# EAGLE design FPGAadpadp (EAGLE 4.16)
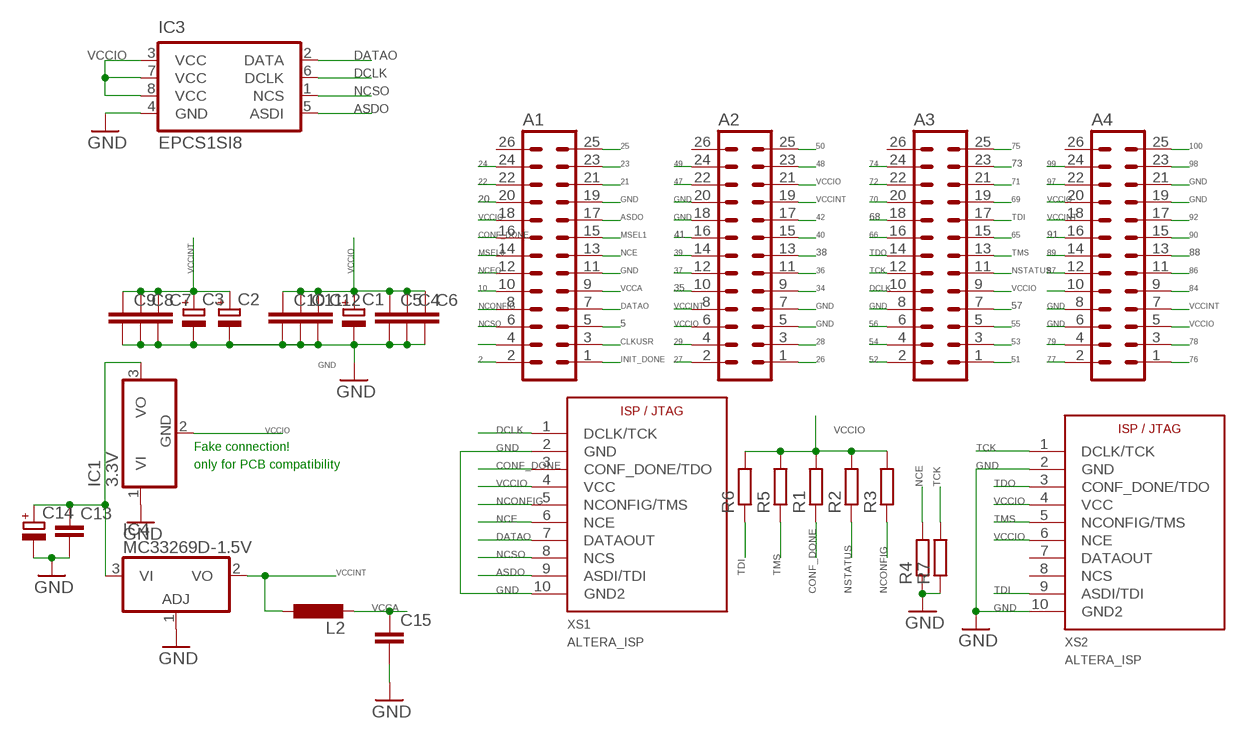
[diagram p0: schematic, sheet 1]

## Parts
A1  ML26  [ML26]
A2  ML26  [ML26]
A3  ML26  [ML26]
A4  ML26  [ML26]
C1  CPOL-EUC/6032-28R  [C/6032-28R]
C2  CPOL-EUC/6032-28R  [C/6032-28R]
C3  CPOL-EUC/6032-28R  [C/6032-28R]
C4  C-EUC1206  [C1206]
C5  C-EUC1206  [C1206]
C6  C-EUC1206  [C1206]
C7  C-EUC1206  [C1206]
C8  C-EUC1206  [C1206]
C9  C-EUC1206  [C1206]
C10  C-EUC1206  [C1206]
C11  C-EUC1206  [C1206]
C12  C-EUC1206  [C1206]
C13  C-EUC1206  [C1206]
C14  CPOL-EUC/6032-28R  [C/6032-28R]
C15  C-EUC1206  [C1206]
IC1  3.3V  LM2937  [TO263-3]
IC3  EPCS1SI8  [SO08]
IC4  MC33269D-1.5V  MC33269D-3.3  [DPACK]
L2  L-EUL4532P  [L4532P]
R1  R-EU_M1206  [M1206]
R2  R-EU_M1206  [M1206]
R3  R-EU_M1206  [M1206]
R4  R-EU_M1206  [M1206]
R5  R-EU_M1206  [M1206]
R6  R-EU_M1206  [M1206]
R7  R-EU_M1206  [M1206]
XS1  ALTERA_ISP  [ALTERA_ISP]
XS2  ALTERA_ISP  [ALTERA_ISP]

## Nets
2: A1.2
4: A1.4
5: A1.5
10: A1.10
20: A1.20
21: A1.21
22: A1.22
23: A1.23
24: A1.24
25: A1.25
26: A2.1
27: A2.2
28: A2.3
29: A2.4
34: A2.9
35: A2.10
36: A2.11
37: A2.12
38: A2.13
39: A2.14
40: A2.15
41: A2.16
42: A2.17
47: A2.22
48: A2.23
49: A2.24
50: A2.25
51: A3.1
52: A3.2
53: A3.3
54: A3.4
55: A3.5
56: A3.6
57: A3.7
65: A3.15
66: A3.16
68: A3.18
69: A3.19
70: A3.20
71: A3.21
72: A3.22
73: A3.23
74: A3.24
75: A3.25
76: A4.1
77: A4.2
78: A4.3
79: A4.4
84: A4.9
85: A4.10
86: A4.11
87: A4.12
88: A4.13
89: A4.14
90: A4.15
91: A4.16
92: A4.17
97: A4.22
98: A4.23
99: A4.24
100: A4.25
ASDO: A1.17 IC3.5(ASDI) XS1.9(ASDI/TDI)
CLKUSR: A1.3
CONF_DONE: A1.16 R1.1 XS1.3(CONF_DONE/TDO)
DATAO: A1.7 IC3.2(DATA) XS1.7(DATAOUT)
DCLK: A3.10 IC3.6(DCLK) XS1.1(DCLK/TCK)
GND: A1.11 A1.19 A2.5 A2.7 A2.18 A2.20 A3.8 A4.6 A4.8 A4.19 A4.21 C1.- C2.- C3.- C4.2 C5.2 C6.2 C7.2 C8.2 C9.2 C10.2 C11.2 C12.2 C13.2 C14.- C15.2 IC1.1(VI) IC3.4(GND) IC4.1(ADJ) R4.1 R7.1 XS1.2(GND) XS1.10(GND2) XS2.2(GND) XS2.10(GND2)
INIT_DONE: A1.1
MSEL0: A1.14
MSEL1: A1.15
NCE: A1.13 R4.2 XS1.6(NCE)
NCEO: A1.12
NCONFIG: A1.8 R3.1 XS1.5(NCONFIG/TMS)
NCSO: A1.6 IC3.1(NCS) XS1.8(NCS)
NSTATUS: A3.11 R2.1
TCK: A3.12 R7.2 XS2.1(DCLK/TCK)
TDI: A3.17 R6.1 XS2.9(ASDI/TDI)
TDO: A3.14 XS2.3(CONF_DONE/TDO)
TMS: A3.13 R5.1 XS2.5(NCONFIG/TMS)
VCC: C13.1 C14.+ IC1.3(VO) IC4.3(VI)
VCCA: A1.9 C15.1 L2.2
VCCINT: A2.8 A2.19 A4.7 A4.18 C2.+ C3.+ C7.1 C8.1 C9.1 IC4.2(VO) L2.1
VCCIO: A1.18 A2.6 A2.21 A3.9 A4.5 A4.20 C1.+ C4.1 C5.1 C6.1 C10.1 C11.1 C12.1 IC1.2(GND) IC3.3(VCC) IC3.7(VCC) IC3.8(VCC) R1.2 R2.2 R3.2 R5.2 R6.2 XS1.4(VCC) XS2.4(VCC) XS2.6(NCE)
Unconnected: A1.26 A2.26 A3.26 A4.26 XS2.7(DATAOUT) XS2.8(NCS)

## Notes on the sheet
- Fake connection!
- only for PCB compatibility

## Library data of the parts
A1-A4 = con-ml:ML26: HARTING
C1-C3 C14 = rcl:CPOL-EU: POLARIZED CAPACITOR, European symbol
C4-C13 C15 = rcl:C-EU: CAPACITOR, European symbol
IC1 = linear:LM2937: LM2937-2.5, LM2937-3.3 400mA and 500mA Voltage Regulators Source: http://cache.national.com/ds/LM/LM2937-2.5.pdf
IC3 = altera-2:EPCS1: 1 Mbit Serial Configuration Device
IC4 = linear:MC33269?*: Adjustable Output Low Dropout Voltage Regulator 800 mA Source: http://www.onsemi.com/pub/Collateral/MC33269-D.PDF
L2 = rcl:L-EU: INDUCTOR, European symbol
R1-R7 = rcl:R-EU_: RESISTOR, European symbol
XS1 XS2 = LevoROMS:ALTERA_ISP

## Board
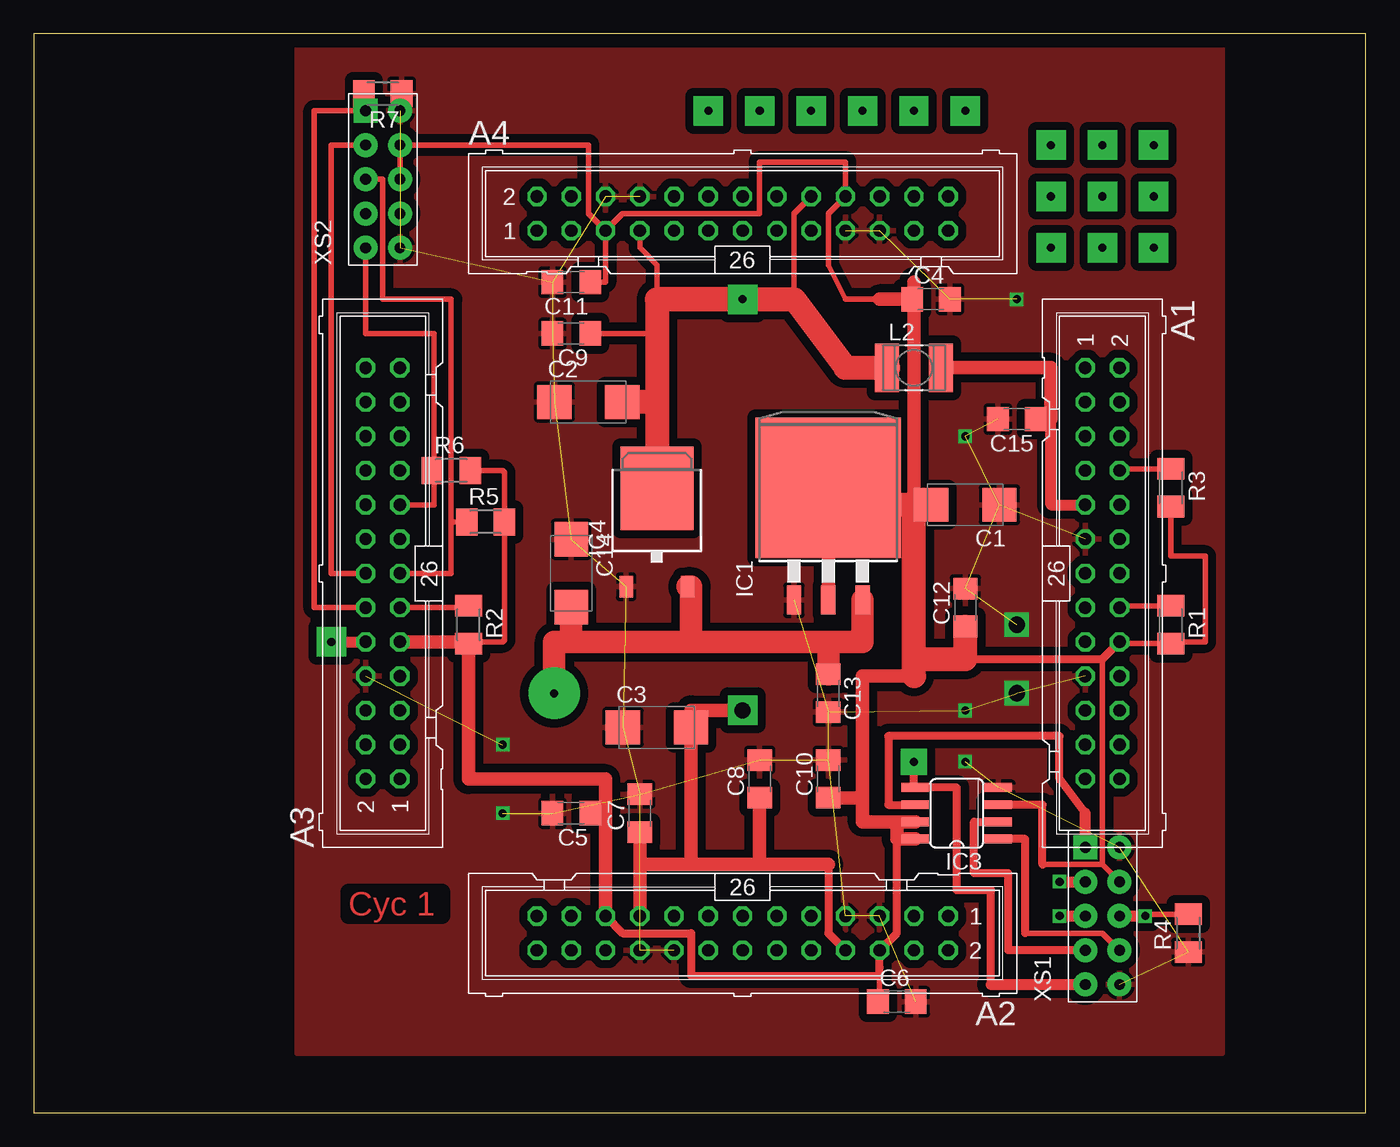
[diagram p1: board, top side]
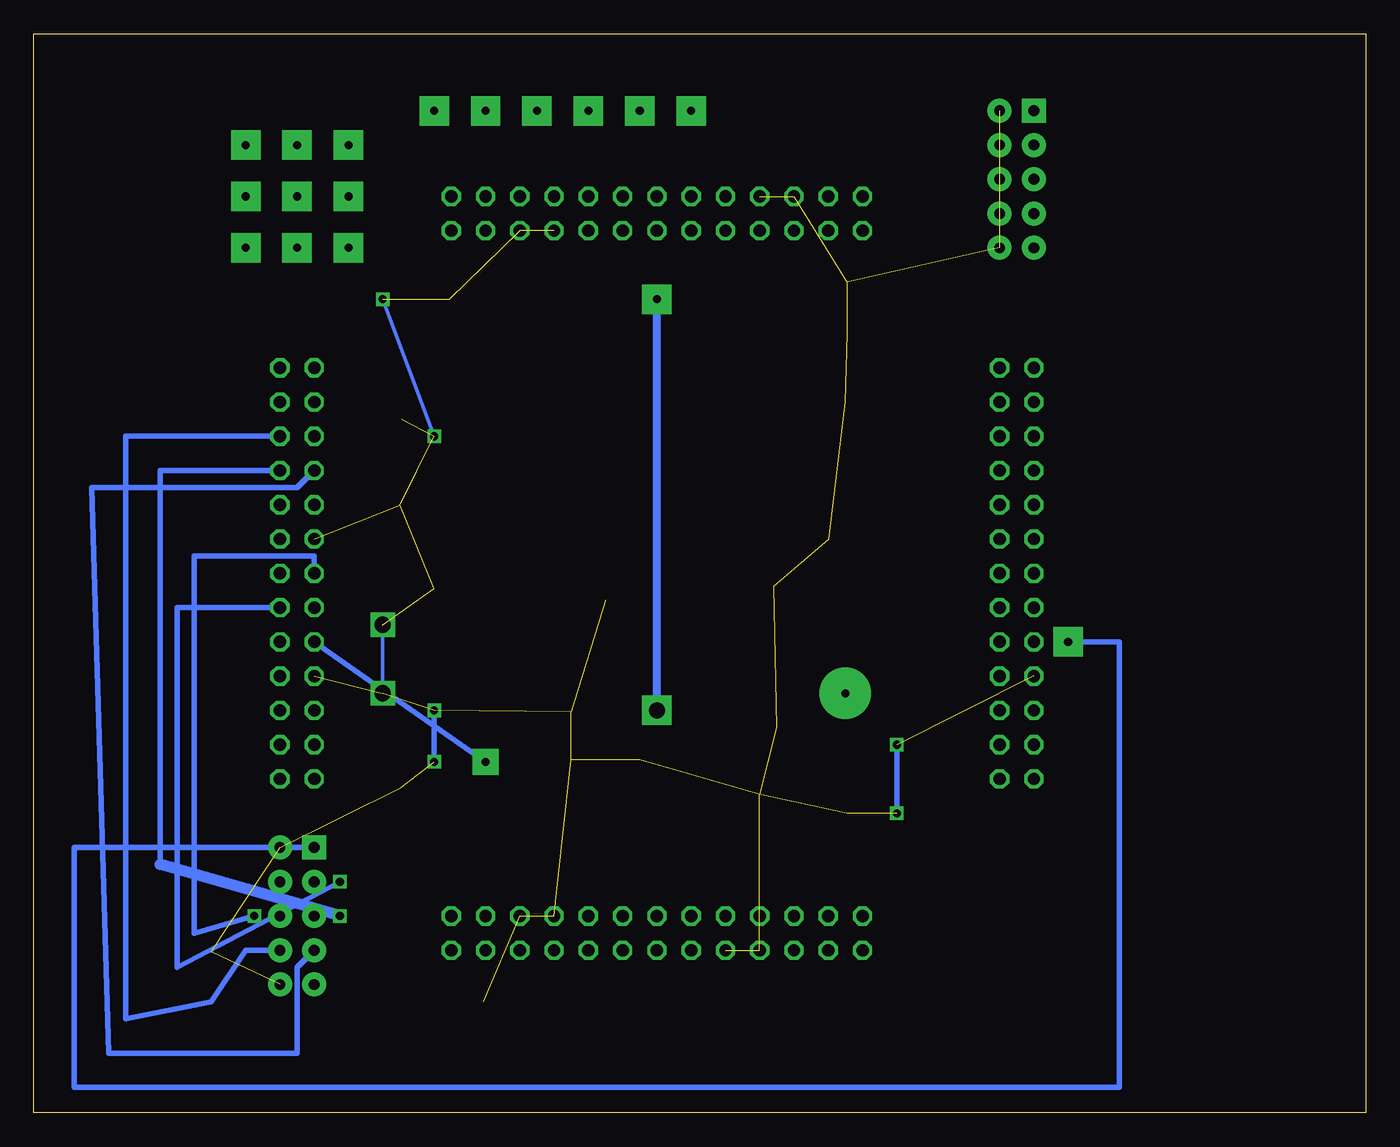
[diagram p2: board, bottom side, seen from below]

Size 98.73 x 80 mm. Coordinates in mm from the lower left corner, seen from the top.
Outline: 0,0 98.73,0 98.73,80 0,80 0,0
Copper layers (1*16): Top 0.035mm / dielectric 1.5mm / Bottom 0.035mm
Design rules "default": minimum track width 10mil, minimum drill 24mil, track to track 8mil, track to pad 8mil, pad to pad 8mil, via to via 8mil, smd to smd 8mil, copper to edge 40mil, drill to drill 8mil, minimum pad ring 10mil, minimum via ring 8mil, stop-mask expansion 4mil, vias tented up to drill 0mil, thermal gap 10mil

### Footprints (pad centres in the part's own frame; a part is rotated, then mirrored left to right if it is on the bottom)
ML26 = drill 0.914 octagon: 1 -15.24,-1.27; 2 -15.24,1.27; 3 -12.7,-1.27; 4 -12.7,1.27; 5 -10.16,-1.27; 6 -10.16,1.27; 7 -7.62,-1.27; 8 -7.62,1.27; 9 -5.08,-1.27; 10 -5.08,1.27; 11 -2.54,-1.27; 12 -2.54,1.27; 13 0,-1.27; 14 0,1.27; 15 2.54,-1.27; 16 2.54,1.27; 17 5.08,-1.27; 18 5.08,1.27; 19 7.62,-1.27; 20 7.62,1.27; 21 10.16,-1.27; 22 10.16,1.27; 23 12.7,-1.27; 24 12.7,1.27; 25 15.24,-1.27; 26 15.24,1.27
C/6032-28R = smd 2.55 x 2.5: + 2.525,0; - -2.525,0
C1206 = smd 1.6 x 1.8: 1 -1.4,0; 2 1.4,0
TO263-3 = smd 1.067 x 2.159: 1 -2.54,-5.791; 2 0,-5.791; 3 2.54,-5.791 | smd 10.8 x 10.41: TAB 0,2.54
SO08 = smd 0.66 x 2.032: 1 -1.905,-3.073; 2 -0.635,-3.073; 3 0.635,-3.073; 4 1.905,-3.073; 5 1.905,3.073; 6 0.635,3.073; 7 -0.635,3.073; 8 -1.905,3.073
DPACK = smd 1 x 1.6: 1 -2.28,-4.8; 3 2.28,-4.8 | smd 5.4 x 6.2: 2 0,2.5
L4532P = smd 1.8 x 3.6: 1 -2,0; 2 2,0
M1206 = smd 1.6 x 2: 1 -1.4,0; 2 1.4,0
ALTERA_ISP = drill 0.8 pad 1.778 square: 1 -1.27,2.54 | drill 0.8 pad 1.778 round: 2 1.27,2.54; 3 -1.27,0; 4 1.27,0; 5 -1.27,-2.54; 6 1.27,-2.54; 7 -1.27,-5.08; 8 1.27,-5.08; 9 -1.27,-7.62; 10 1.27,-7.62

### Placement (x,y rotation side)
A1  79.21,40 270 top
A2  52.54,13.33 180 top
A3  25.87,40 90 top
A4  52.54,66.67 0 top
C1  69.05,45.08 180 top
C2  41.11,52.7 0 top
C3  46.19,28.57 0 top
C4  66.51,60.32 0 top
C5  39.84,22.22 180 top
C6  63.97,8.25 0 top
C7  44.92,22.22 90 top
C8  53.81,24.76 90 top
C9  39.84,57.78 180 top
C10  58.89,24.76 90 top
C11  39.84,61.59 180 top
C12  69.05,37.46 90 top
C13  58.89,31.11 270 top
C14  39.84,40 270 top
C15  72.86,51.43 180 top
IC1  58.89,43.81 0 top
IC3  68.41,22.22 90 top
IC4  46.19,43.81 0 top
L2  65.24,55.24 0 top
R1  84.29,36.19 270 top
R2  32.22,36.19 270 top
R3  84.29,46.35 270 top
R4  85.56,13.33 90 top
R5  33.49,43.81 0 top
R6  30.95,47.62 0 top
R7  25.87,75.56 180 top
XS1  79.21,17.14 0 top
XS2  25.87,71.75 0 top

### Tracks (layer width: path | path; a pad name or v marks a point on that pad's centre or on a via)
ASDO  (via drill 0.6 pad 1.93)
  Top 0.406: IC3.5 arc-180 65.24,24.12
  Top 0.61: IC3.5 68.41,24.12 68.41,16.5 70.95,16.5 70.95,9.52 | 65.24,24.12 v65.24,26.03
  Top 0.813: 70.95,9.52 XS1.9
  Bottom 0.406: v65.24,26.03 A1.17
CONF_DONE  (via drill 0.6)
  Top 0.406: R1.1 80.48,37.59 A1.16
  Top 0.813: v76.03,17.14 XS1.3
  Bottom 0.406: A1.16 88.1,37.46 88.1,10.79 v76.03,17.14
DATAO
  Top 0.61: IC3.2 69.69,21.58 69.69,17.77 72.22,17.77 72.22,12.06 XS1.7
  Bottom 0.406: A1.7 79.21,46.35 94.45,46.35 93.18,4.44 79.21,4.44 79.21,10.79 XS1.7
DCLK  (via drill 0.6 pad 2.18)
  Top 0.61: 77.94,22.22 76.03,24.76 76.03,27.93 63.34,27.93 63.34,22.86 IC3.6
  Top 0.813: XS1.1 77.94,22.22 | v22.06,34.92 A3.10
  Bottom 0.406: XS1.1 95.72,19.68 95.72,1.9 18.25,1.9 18.25,34.92 v22.06,34.92
GND  (via drill 0.6, 1.2)  (37 unrouted)
  Top 0.406: R7.1 27.27,74.42 XS2.2
  Bottom 0.254: v72.86,31.11 v72.86,36.19 | v69.05,50.16 v72.86,60.32
  Bottom 0.406: v69.05,26.03 v69.05,29.84 | v34.76,22.22 v34.76,27.3
  pour Top (isolate 0.61): 19.52,79.37 19.52,4.44 88.1,4.44 88.1,79.37
N$10  (via drill 0.6 pad 2.18)
  other vias: 75.4,71.75
N$11  (via drill 0.6 pad 2.18)
  other vias: 75.4,67.94
N$12  (via drill 0.6 pad 2.18)
  other vias: 75.4,64.13
N$13  (via drill 0.6 pad 2.18)
  other vias: 79.21,64.13
N$14  (via drill 0.6 pad 2.18)
  other vias: 79.21,67.94
N$15  (via drill 0.6 pad 2.18)
  other vias: 79.21,71.75
N$16  (via drill 0.6 pad 2.18)
  other vias: 83.02,71.75
N$17  (via drill 0.6 pad 2.18)
  other vias: 83.02,67.94
N$18  (via drill 0.6 pad 2.18)
  other vias: 83.02,64.13
N$25  (via drill 0.6 pad 2.18)
  other vias: 50,74.29
N$26  (via drill 0.6 pad 2.18)
  other vias: 53.81,74.29
N$27  (via drill 0.6 pad 2.18)
  other vias: 57.62,74.29
N$28  (via drill 0.6 pad 2.18)
  other vias: 61.43,74.29
N$29  (via drill 0.6 pad 2.18)
  other vias: 65.24,74.29
N$30  (via drill 0.6 pad 2.18)
  other vias: 69.05,74.29
NCE  (via drill 0.6)
  Top 0.406: R4.2 80.48,14.73 XS1.6
  Top 0.813: XS1.6 v82.39,14.6
  Bottom 0.406: v82.39,14.6 86.83,13.33 86.83,41.27 77.94,41.27 A1.13
NCONFIG  (via drill 0.6)
  Top 0.406: R3.1 80.48,47.75 A1.8
  Top 0.813: v76.03,14.6 XS1.5
  Bottom 0.406: A1.8 89.37,47.62 89.37,18.41
  Bottom 0.813: v76.03,14.6 89.37,18.41
NCSO
  Top 0.406: 73.5,13.33 79.21,13.33 XS1.8
  Top 0.61: IC3.1 73.5,20.31 73.5,13.33
  Bottom 0.406: A1.6 91.91,50.16 91.91,6.98 85.56,8.25 83.02,12.06 XS1.8
NSTATUS
  Top 0.406: R2.1 32.22,37.46 A3.11
TCK
  Top 0.406: A3.12 20.79,37.46 20.79,74.29 XS2.1 24.47,74.42 R7.2
TDI
  Top 0.406: XS2.9 24.6,57.78 29.68,57.78 29.68,47.62 | 29.68,47.62 29.68,45.08 A3.17 | 29.68,47.62 R6.1
TDO
  Top 0.406: XS2.3 22.06,71.75 22.06,40 A3.14
TMS
  Top 0.406: XS2.5 25.87,69.21 25.87,60.32 30.95,60.32 30.95,43.81 | 30.95,43.81 30.95,40 A3.13 | 30.95,43.81 R5.1
VCC  (via drill 0.6 pad 3.81)
  Top 0.406: IC1.3 61.43,38.1
  Top 1.676: 39.84,34.92 C14.+ | v38.57,31.11 38.57,34.92 39.84,34.92 | 39.84,34.92 48.73,34.92 | 48.73,34.92 58.89,34.92 | 58.89,34.92 61.43,34.92 IC1.3 | IC4.3 48.73,39.01 48.73,34.92 | 58.89,34.92 C13.1
VCCA
  Top 0.813: A1.9 75.4,45.08 75.4,51.43 C15.1
  Top 1.016: 75.4,51.43 75.4,55.24 L2.2
VCCINT  (via drill 0.6 pad 2.18, 1.2 pad 2.18)
  Top 0.406: A4.18 56.35,66.67 56.35,60.32 | 46.19,57.78 C9.1 | A4.7 44.92,64.13 46.19,62.86 46.19,60.32
  Top 0.61: A2.8 58.89,13.33 58.89,18.41
  Top 0.813: 48.73,27.3 C3.+
  Top 1.016: 48.73,18.41 48.73,27.3 48.73,29.84 v52.54,29.84 | 44.92,18.41 48.73,18.41 | 48.73,18.41 53.81,18.41 | 53.81,18.41 C8.1 | 53.81,18.41 58.89,18.41 | 44.92,18.41 C7.1 | A2.19 44.92,18.41
  Top 1.778: 46.19,52.7 IC4.2 | 46.19,52.7 C2.+ | 46.19,60.32 46.19,57.78 46.19,52.7 | v52.54,60.32 46.19,60.32 | 46.19,60.32 56.35,60.32 60.16,55.24 L2.1 63.34,55.24
  Bottom 0.61: v52.54,29.84 v52.54,60.32
VCCIO
  Top 0.406: 79.21,18.41 74.77,18.41 | 79.21,18.41 XS1.4 | 79.21,33.65 79.21,18.41 | A4.5 42.38,61.59 C11.1 41.11,61.59 | 62.7,60.32 60.16,60.32 58.89,62.86 58.89,66.67 A4.20 60.16,70.48 53.81,70.48 53.81,66.67 43.65,66.67 A4.5 | A1.18 80.48,34.79 R1.2 84.29,34.92 86.83,34.92 86.83,41.27 84.29,41.27 R3.2 | C6.1 62.7,8.25 62.7,10.79 | XS2.6 XS2.4 41.11,71.75 41.11,66.67 A4.5 | 32.22,34.92 34.76,34.92 34.89,35.05 R5.2 34.89,47.49 34.76,47.62 R6.2 32.22,47.62
  Top 0.61: 63.97,20.31 63.97,13.33 A2.6 62.7,10.79 62.7,10.16 48.73,10.16 48.73,13.33 43.65,13.33 A2.21 | A1.18 79.21,33.65 69.05,33.65 | IC3.3 74.77,22.86 74.77,18.41
  Top 0.813: 65.24,61.59 C4.1 | 42.38,22.22 C5.1 | 65.24,45.08 C1.+ | 61.43,23.49 61.43,23.36
  Top 1.016: 65.24,45.08 65.24,61.59 | C4.1 62.7,60.32 | 63.97,21.58 63.97,20.31 IC3.8 | 63.97,21.58 61.43,21.58 61.43,23.49 61.43,32.38 65.24,32.38 | A2.21 42.38,22.22 42.38,24.76 32.22,24.76 R2.2 32.22,34.92 A3.9 | 63.97,21.58 IC3.7 | 58.89,45.08 IC1.2 | 61.43,23.36 C10.1
  Top 1.778: 65.24,32.38 65.24,33.65 | 65.24,33.65 65.24,45.08 58.89,45.08 | 65.24,33.65 69.05,33.65 C12.1

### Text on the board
Top: Cyc 1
